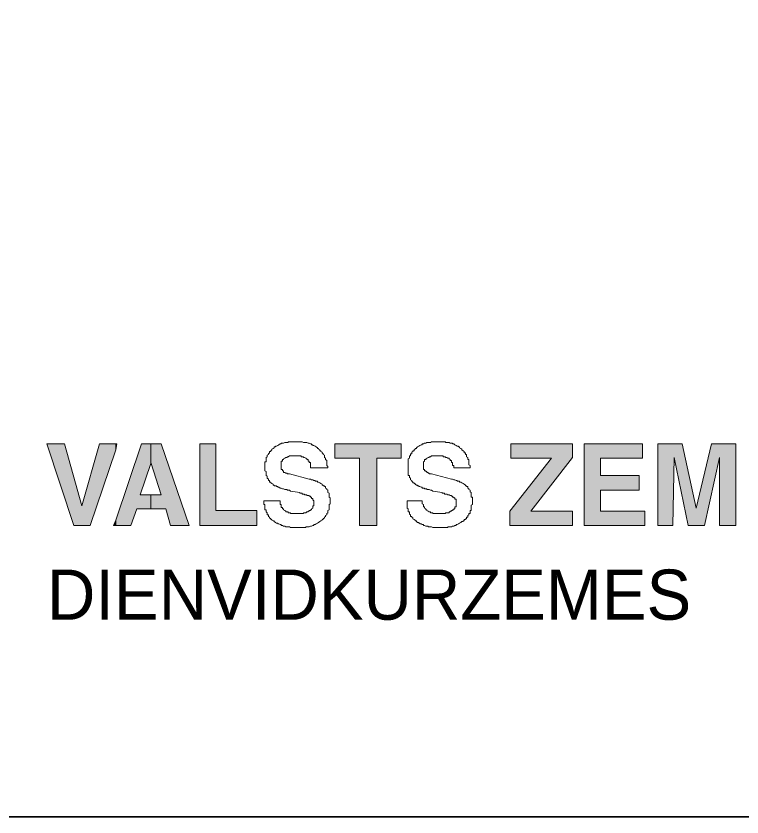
# Model space of a CAD drawing. Extents: x 308460 to 314812, y 245206 to 253414.
# Drawn here: x 314384.6 to 314574.6, y 245420.8 to 245630.3 of the extents above; entities that cross this region are included whole.
import ezdxf

# ---------------------------------------------------------------- set-up
doc = ezdxf.new("R2010")
doc.units = 0
doc.header["$LTSCALE"] = 11
doc.layers.add('57', color=7, linetype='Continuous', lineweight=13)

msp = doc.modelspace()

# ---------------------------------------------------------------- hatches: boundary and pattern name
at = {"layer": '57'}
for points in [[(314401.85, 245502.15), (314406.43, 245518.37), (314410.7, 245518.37), (314410.7, 245516.8), (314403.99, 245497.06), (314399.71, 245497.06), (314392.7, 245518.37), (314397.28, 245518.37)], [(314419.85, 245513.29), (314417.11, 245505.08), (314419.85, 245505.08), (314419.85, 245501.37), (314416.19, 245501.37), (314414.66, 245497.06), (314410.7, 245497.06), (314410.7, 245498.43), (314417.41, 245518.37), (314419.85, 245518.37)], [(314410.7, 245516.8), (314410.7, 245518.37), (314411.01, 245518.37)], [(314419.85, 245513.49), (314419.85, 245518.37), (314422.58, 245518.37), (314429.92, 245497.06), (314425.04, 245497.06), (314423.82, 245501.37), (314419.85, 245501.37), (314419.85, 245505.08), (314422.58, 245505.08)], [(314436.94, 245518.37), (314436.94, 245500.97), (314447.61, 245500.97), (314447.61, 245497.06), (314432.67, 245497.06), (314432.67, 245518.37)], [(314479.04, 245514.66), (314479.04, 245497.06), (314474.47, 245497.06), (314474.47, 245514.66), (314468.07, 245514.66), (314468.07, 245518.37), (314485.44, 245518.37), (314485.44, 245514.66)], [(314530.3, 245500.78), (314530.3, 245497.06), (314513.82, 245497.06), (314513.82, 245500.78), (314524.8, 245514.66), (314514.13, 245514.66), (314514.13, 245518.37), (314530.3, 245518.37), (314530.3, 245514.85), (314519.32, 245500.78)], [(314548.6, 245518.37), (314548.6, 245514.66), (314537.62, 245514.66), (314537.62, 245510.16), (314547.69, 245510.16), (314547.69, 245506.25), (314537.62, 245506.25), (314537.62, 245500.78), (314549.21, 245500.78), (314549.21, 245497.06), (314533.34, 245497.06), (314533.34, 245518.37)], [(314573.01, 245518.37), (314573.01, 245497.06), (314568.75, 245497.06), (314568.75, 245514.85), (314564.78, 245497.06), (314560.51, 245497.06), (314556.84, 245514.85), (314556.54, 245497.06), (314552.58, 245497.06), (314552.58, 245518.37), (314558.98, 245518.37), (314562.64, 245501.56), (314566.61, 245518.37)], [(314410.7, 245497.06), (314410.09, 245497.06), (314410.7, 245498.43)]]:
    msp.add_hatch(color=256, dxfattribs=at).paths.add_polyline_path(points)

# ---------------------------------------------------------------- linework, layer by layer
at = {"layer": '57', "lineweight": 35}
msp.add_lwpolyline([(314811.5, 253140.4), (312000.01, 253140.4), (312000.01, 245420.78), (314811.5, 245420.78)], close=True, dxfattribs=at)
at = {"layer": '57'}
for points in [[(314401.85, 245502.15), (314406.43, 245518.37), (314410.7, 245518.37), (314410.7, 245516.8), (314403.99, 245497.06), (314399.71, 245497.06), (314392.7, 245518.37), (314397.28, 245518.37)], [(314419.85, 245513.29), (314417.11, 245505.08), (314419.85, 245505.08), (314419.85, 245501.37), (314416.19, 245501.37), (314414.66, 245497.06), (314410.7, 245497.06), (314410.7, 245498.43), (314417.41, 245518.37), (314419.85, 245518.37)], [(314410.7, 245516.8), (314410.7, 245518.37), (314411.01, 245518.37)], [(314419.85, 245513.49), (314419.85, 245518.37), (314422.58, 245518.37), (314429.92, 245497.06), (314425.04, 245497.06), (314423.82, 245501.37), (314419.85, 245501.37), (314419.85, 245505.08), (314422.58, 245505.08)], [(314436.94, 245518.37), (314436.94, 245500.97), (314447.61, 245500.97), (314447.61, 245497.06), (314432.67, 245497.06), (314432.67, 245518.37)], [(314479.04, 245514.66), (314479.04, 245497.06), (314474.47, 245497.06), (314474.47, 245514.66), (314468.07, 245514.66), (314468.07, 245518.37), (314485.44, 245518.37), (314485.44, 245514.66)], [(314530.3, 245500.78), (314530.3, 245497.06), (314513.82, 245497.06), (314513.82, 245500.78), (314524.8, 245514.66), (314514.13, 245514.66), (314514.13, 245518.37), (314530.3, 245518.37), (314530.3, 245514.85), (314519.32, 245500.78)], [(314548.6, 245518.37), (314548.6, 245514.66), (314537.62, 245514.66), (314537.62, 245510.16), (314547.69, 245510.16), (314547.69, 245506.25), (314537.62, 245506.25), (314537.62, 245500.78), (314549.21, 245500.78), (314549.21, 245497.06), (314533.34, 245497.06), (314533.34, 245518.37)], [(314573.01, 245518.37), (314573.01, 245497.06), (314568.75, 245497.06), (314568.75, 245514.85), (314564.78, 245497.06), (314560.51, 245497.06), (314556.84, 245514.85), (314556.54, 245497.06), (314552.58, 245497.06), (314552.58, 245518.37), (314558.98, 245518.37), (314562.64, 245501.56), (314566.61, 245518.37)], [(314410.7, 245497.06), (314410.09, 245497.06), (314410.7, 245498.43)]]:
    msp.add_lwpolyline(points, close=True, dxfattribs=at)
for points in [[(314452.19, 245507.42), (314452.19, 245507.63), (314451.9, 245507.63), (314451.9, 245507.81), (314451.58, 245508.01), (314451.27, 245508.2), (314451.27, 245508.41), (314450.98, 245508.41), (314450.98, 245508.6), (314450.98, 245508.78), (314450.66, 245508.78), (314450.66, 245508.99), (314450.66, 245509.18), (314450.37, 245509.38), (314450.37, 245509.56), (314450.37, 245509.77), (314450.37, 245509.97), (314450.05, 245510.16), (314450.05, 245510.36), (314450.05, 245510.55), (314450.05, 245510.75), (314450.05, 245510.94), (314450.05, 245511.14), (314449.75, 245511.33), (314449.75, 245511.52), (314449.75, 245511.73), (314449.75, 245511.92), (314449.75, 245512.11), (314449.75, 245512.3), (314449.75, 245512.51), (314449.75, 245512.7), (314449.75, 245512.89), (314449.75, 245513.08), (314449.75, 245513.29), (314449.75, 245513.49), (314449.75, 245513.67), (314450.05, 245513.67), (314450.05, 245513.87), (314450.05, 245514.06), (314450.05, 245514.26), (314450.05, 245514.45), (314450.05, 245514.66), (314450.05, 245514.85), (314450.37, 245515.04), (314450.37, 245515.24), (314450.37, 245515.43), (314450.66, 245515.63), (314450.66, 245515.82), (314450.98, 245516.02), (314450.98, 245516.22), (314450.98, 245516.41), (314451.27, 245516.41), (314451.27, 245516.61), (314451.58, 245516.8), (314451.58, 245517), (314451.9, 245517.19), (314452.19, 245517.39), (314452.19, 245517.59), (314452.5, 245517.59), (314452.5, 245517.78), (314452.8, 245517.78), (314453.11, 245517.97), (314453.4, 245518.17), (314453.71, 245518.37), (314454.03, 245518.37), (314454.03, 245518.56), (314454.33, 245518.56), (314454.64, 245518.56), (314454.93, 245518.76), (314455.24, 245518.76), (314455.56, 245518.76), (314455.85, 245518.76), (314455.85, 245518.95), (314456.16, 245518.95), (314456.46, 245518.95), (314456.77, 245518.95), (314457.07, 245518.95), (314457.38, 245518.95), (314457.68, 245518.95), (314457.99, 245518.95), (314458.29, 245518.95), (314458.6, 245518.95), (314458.9, 245518.95), (314459.21, 245518.95), (314459.51, 245518.95), (314459.82, 245518.76), (314460.12, 245518.76), (314460.43, 245518.76), (314460.73, 245518.76), (314461.04, 245518.56), (314461.34, 245518.56), (314461.64, 245518.37), (314461.95, 245518.37), (314461.95, 245518.17), (314462.25, 245518.17), (314462.25, 245517.97), (314462.57, 245517.97), (314462.88, 245517.78), (314463.17, 245517.59), (314463.49, 245517.39), (314463.49, 245517.19)], [(314489.72, 245507.63), (314489.41, 245507.63), (314489.11, 245507.81), (314489.11, 245508.01), (314488.8, 245508.01), (314488.8, 245508.2), (314488.5, 245508.2), (314488.5, 245508.41), (314488.2, 245508.6), (314488.2, 245508.78), (314487.9, 245508.99), (314487.9, 245509.18), (314487.9, 245509.38), (314487.59, 245509.56), (314487.59, 245509.77), (314487.59, 245509.97), (314487.59, 245510.16), (314487.27, 245510.16), (314487.27, 245510.36), (314487.27, 245510.55), (314487.27, 245510.75), (314487.27, 245510.94), (314487.27, 245511.14), (314487.27, 245511.33), (314487.27, 245511.52), (314487.27, 245511.73), (314487.27, 245511.92), (314487.27, 245512.11), (314487.27, 245512.3), (314487.27, 245512.51), (314487.27, 245512.7), (314487.27, 245512.89), (314487.27, 245513.08), (314487.27, 245513.29), (314487.27, 245513.49), (314487.27, 245513.67), (314487.27, 245513.87), (314487.27, 245514.06), (314487.27, 245514.26), (314487.27, 245514.45), (314487.59, 245514.66), (314487.59, 245514.85), (314487.59, 245515.04), (314487.59, 245515.24), (314487.9, 245515.24), (314487.9, 245515.43), (314487.9, 245515.63), (314487.9, 245515.82), (314488.2, 245515.82), (314488.2, 245516.02), (314488.2, 245516.22), (314488.5, 245516.41), (314488.5, 245516.61), (314488.8, 245516.61), (314488.8, 245516.8), (314489.11, 245517), (314489.11, 245517.19), (314489.41, 245517.19), (314489.41, 245517.39), (314489.72, 245517.59), (314490.03, 245517.78), (314490.33, 245517.97), (314490.63, 245518.17), (314490.93, 245518.17), (314490.93, 245518.37), (314491.24, 245518.37), (314491.55, 245518.56), (314491.85, 245518.56), (314492.16, 245518.76), (314492.46, 245518.76), (314492.76, 245518.76), (314493.09, 245518.76), (314493.37, 245518.95), (314493.69, 245518.95), (314494, 245518.95), (314494.3, 245518.95), (314494.6, 245518.95), (314494.91, 245518.95), (314495.22, 245518.95), (314495.51, 245518.95), (314495.83, 245518.95), (314496.12, 245518.95), (314496.43, 245518.95), (314496.75, 245518.95), (314497.04, 245518.95), (314497.04, 245518.76), (314497.35, 245518.76), (314497.65, 245518.76), (314497.96, 245518.76), (314498.25, 245518.56), (314498.56, 245518.56), (314498.88, 245518.56), (314498.88, 245518.37), (314499.18, 245518.37), (314499.49, 245518.17), (314499.79, 245517.97), (314500.09, 245517.78), (314500.4, 245517.78), (314500.4, 245517.59), (314500.7, 245517.59), (314500.7, 245517.39)], [(314463.49, 245517.19), (314463.78, 245517.19), (314463.78, 245517), (314464.09, 245516.8), (314464.09, 245516.61), (314464.4, 245516.61), (314464.4, 245516.41), (314464.7, 245516.22), (314464.7, 245516.02), (314465.01, 245515.82), (314465.01, 245515.63), (314465.31, 245515.43), (314465.31, 245515.24), (314465.31, 245515.04), (314465.31, 245514.85), (314465.62, 245514.66), (314465.62, 245514.45), (314465.62, 245514.26), (314465.92, 245514.06), (314465.92, 245513.87), (314465.92, 245513.67), (314465.92, 245513.49), (314465.92, 245513.29), (314465.92, 245513.08), (314465.92, 245512.89), (314465.92, 245512.7), (314466.22, 245512.51), (314466.22, 245512.3), (314466.22, 245512.11), (314461.64, 245512.11), (314461.64, 245512.3), (314461.64, 245512.51), (314461.64, 245512.7), (314461.64, 245512.89), (314461.64, 245513.08), (314461.64, 245513.29), (314461.64, 245513.49), (314461.34, 245513.49), (314461.34, 245513.67), (314461.34, 245513.87), (314461.04, 245513.87), (314461.04, 245514.06), (314461.04, 245514.26), (314460.73, 245514.26), (314460.73, 245514.45), (314460.43, 245514.66), (314460.12, 245514.85), (314459.82, 245514.85), (314459.82, 245515.04), (314459.51, 245515.04), (314459.21, 245515.04), (314459.21, 245515.24), (314458.9, 245515.24), (314458.6, 245515.24), (314458.29, 245515.24), (314457.99, 245515.24), (314457.68, 245515.24), (314457.38, 245515.24), (314457.07, 245515.24), (314456.77, 245515.24), (314456.46, 245515.24), (314456.16, 245515.24), (314455.85, 245515.04), (314455.56, 245515.04), (314455.56, 245514.85), (314455.24, 245514.85), (314454.93, 245514.66), (314454.64, 245514.45), (314454.64, 245514.26), (314454.33, 245514.26), (314454.33, 245514.06), (314454.33, 245513.87), (314454.03, 245513.87), (314454.03, 245513.67), (314454.03, 245513.49), (314454.03, 245513.29), (314454.03, 245513.08), (314454.03, 245512.89), (314454.03, 245512.7), (314454.03, 245512.51), (314454.03, 245512.3), (314454.03, 245512.11), (314454.03, 245511.92), (314454.03, 245511.73), (314454.33, 245511.73), (314454.33, 245511.52), (314454.33, 245511.33), (314454.64, 245511.33), (314454.64, 245511.14), (314454.64, 245510.94), (314454.93, 245510.94), (314455.24, 245510.75), (314455.56, 245510.75), (314455.56, 245510.55), (314455.85, 245510.55), (314456.16, 245510.55), (314461.34, 245509.18), (314461.64, 245509.18), (314461.95, 245508.99), (314462.25, 245508.99), (314462.57, 245508.78)], [(314500.7, 245517.39), (314501.01, 245517.19), (314501.31, 245517), (314501.31, 245516.8), (314501.62, 245516.61), (314501.92, 245516.41), (314501.92, 245516.22), (314501.92, 245516.02), (314502.23, 245516.02), (314502.23, 245515.82), (314502.23, 245515.63), (314502.54, 245515.63), (314502.54, 245515.43), (314502.54, 245515.24), (314502.54, 245515.04), (314502.84, 245514.85), (314502.84, 245514.66), (314502.84, 245514.45), (314502.84, 245514.26), (314503.14, 245514.26), (314503.14, 245514.06), (314503.14, 245513.87), (314503.14, 245513.67), (314503.14, 245513.49), (314503.14, 245513.29), (314503.14, 245513.08), (314503.14, 245512.89), (314503.45, 245512.7), (314503.45, 245512.51), (314503.45, 245512.3), (314503.45, 245512.11), (314499.18, 245512.11), (314499.18, 245512.3), (314499.18, 245512.51), (314499.18, 245512.7), (314498.88, 245512.7), (314498.88, 245512.89), (314498.88, 245513.08), (314498.88, 245513.29), (314498.88, 245513.49), (314498.56, 245513.49), (314498.56, 245513.67), (314498.56, 245513.87), (314498.56, 245514.06), (314498.25, 245514.06), (314498.25, 245514.26), (314497.96, 245514.45), (314497.96, 245514.66), (314497.65, 245514.66), (314497.35, 245514.85), (314497.04, 245514.85), (314497.04, 245515.04), (314496.75, 245515.04), (314496.43, 245515.04), (314496.43, 245515.24), (314496.12, 245515.24), (314495.83, 245515.24), (314495.51, 245515.24), (314495.22, 245515.24), (314494.91, 245515.24), (314494.6, 245515.24), (314494.3, 245515.24), (314494, 245515.24), (314493.69, 245515.24), (314493.37, 245515.24), (314493.09, 245515.04), (314492.76, 245515.04), (314492.76, 245514.85), (314492.46, 245514.85), (314492.16, 245514.66), (314492.16, 245514.45), (314491.85, 245514.45), (314491.85, 245514.26), (314491.55, 245514.26), (314491.55, 245514.06), (314491.55, 245513.87), (314491.24, 245513.67), (314491.24, 245513.49), (314491.24, 245513.29), (314491.24, 245513.08), (314491.24, 245512.89), (314491.24, 245512.7), (314491.24, 245512.51), (314491.24, 245512.3), (314491.24, 245512.11), (314491.24, 245511.92), (314491.24, 245511.73), (314491.55, 245511.73), (314491.55, 245511.52), (314491.55, 245511.33), (314491.85, 245511.33), (314491.85, 245511.14), (314492.16, 245511.14), (314492.16, 245510.94), (314492.46, 245510.94), (314492.46, 245510.75), (314492.76, 245510.75), (314492.76, 245510.55), (314493.09, 245510.55), (314493.37, 245510.55), (314498.56, 245509.18)], [(314462.57, 245508.78), (314462.88, 245508.78), (314462.88, 245508.6), (314463.17, 245508.6), (314463.49, 245508.6), (314463.49, 245508.41), (314463.78, 245508.41), (314464.09, 245508.2), (314464.4, 245508.01), (314464.7, 245507.81), (314464.7, 245507.63), (314465.01, 245507.63), (314465.01, 245507.42), (314465.31, 245507.42), (314465.31, 245507.23), (314465.62, 245507.23), (314465.62, 245507.03), (314465.62, 245506.83), (314465.92, 245506.64), (314465.92, 245506.44), (314466.22, 245506.25), (314466.22, 245506.05), (314466.22, 245505.86), (314466.22, 245505.67), (314466.53, 245505.47), (314466.53, 245505.27), (314466.53, 245505.08), (314466.53, 245504.88), (314466.53, 245504.69), (314466.53, 245504.49), (314466.84, 245504.3), (314466.84, 245504.1), (314466.84, 245503.9), (314466.84, 245503.71), (314466.84, 245503.52), (314466.84, 245503.31), (314466.84, 245503.13), (314466.84, 245502.93), (314466.84, 245502.74), (314466.53, 245502.53), (314466.53, 245502.33), (314466.53, 245502.15), (314466.53, 245501.96), (314466.53, 245501.75), (314466.53, 245501.56), (314466.53, 245501.37), (314466.53, 245501.16), (314466.22, 245500.97), (314466.22, 245500.78), (314466.22, 245500.59), (314466.22, 245500.38), (314465.92, 245500.2), (314465.92, 245500), (314465.92, 245499.8), (314465.62, 245499.61), (314465.62, 245499.41), (314465.31, 245499.22), (314465.31, 245499.02), (314465.01, 245498.82), (314465.01, 245498.63), (314464.7, 245498.63), (314464.7, 245498.43), (314464.4, 245498.24), (314464.09, 245498.04), (314463.78, 245497.85), (314463.49, 245497.65), (314463.17, 245497.46), (314462.88, 245497.26), (314462.57, 245497.26), (314462.57, 245497.06), (314462.25, 245497.06), (314461.95, 245496.87), (314461.64, 245496.87), (314461.34, 245496.67), (314461.04, 245496.67), (314460.73, 245496.67), (314460.43, 245496.67), (314460.43, 245496.48), (314460.12, 245496.48), (314459.82, 245496.48), (314459.51, 245496.48), (314459.21, 245496.48), (314458.9, 245496.48), (314458.6, 245496.48), (314458.29, 245496.48), (314457.99, 245496.48), (314457.68, 245496.48), (314457.38, 245496.48), (314457.07, 245496.48), (314456.77, 245496.48), (314456.46, 245496.48), (314456.16, 245496.67), (314455.85, 245496.67), (314455.56, 245496.67), (314455.24, 245496.67), (314454.93, 245496.87), (314454.64, 245496.87), (314454.33, 245497.06), (314454.03, 245497.06), (314454.03, 245497.26), (314453.71, 245497.26)], [(314498.56, 245509.18), (314498.88, 245509.18), (314499.18, 245508.99), (314499.49, 245508.99), (314499.79, 245508.78), (314500.09, 245508.78), (314500.09, 245508.6), (314500.4, 245508.6), (314500.7, 245508.6), (314500.7, 245508.41), (314501.01, 245508.41), (314501.31, 245508.2), (314501.62, 245508.01), (314501.92, 245507.81), (314502.23, 245507.63), (314502.23, 245507.42), (314502.54, 245507.42), (314502.54, 245507.23), (314502.84, 245507.23), (314502.84, 245507.03), (314502.84, 245506.83), (314503.14, 245506.64), (314503.14, 245506.44), (314503.45, 245506.25), (314503.45, 245506.05), (314503.45, 245505.86), (314503.75, 245505.67), (314503.75, 245505.47), (314503.75, 245505.27), (314503.75, 245505.08), (314503.75, 245504.88), (314503.75, 245504.69), (314503.75, 245504.49), (314504.07, 245504.49), (314504.07, 245504.3), (314504.07, 245504.1), (314504.07, 245503.9), (314504.07, 245503.71), (314504.07, 245503.52), (314504.07, 245503.31), (314504.07, 245503.13), (314504.07, 245502.93), (314504.07, 245502.74), (314504.07, 245502.53), (314503.75, 245502.33), (314503.75, 245502.15), (314503.75, 245501.96), (314503.75, 245501.75), (314503.75, 245501.56), (314503.75, 245501.37), (314503.75, 245501.16), (314503.75, 245500.97), (314503.45, 245500.97), (314503.45, 245500.78), (314503.45, 245500.59), (314503.45, 245500.38), (314503.45, 245500.2), (314503.14, 245500.2), (314503.14, 245500), (314503.14, 245499.8), (314502.84, 245499.61), (314502.84, 245499.41), (314502.84, 245499.22), (314502.54, 245499.22), (314502.54, 245499.02), (314502.54, 245498.82), (314502.23, 245498.82), (314502.23, 245498.63), (314501.92, 245498.63), (314501.92, 245498.43), (314501.92, 245498.24), (314501.62, 245498.24), (314501.62, 245498.04), (314501.31, 245498.04), (314501.01, 245497.85), (314500.7, 245497.65), (314500.4, 245497.46), (314500.09, 245497.26), (314499.79, 245497.26), (314499.79, 245497.06), (314499.49, 245497.06), (314499.18, 245496.87), (314498.88, 245496.87), (314498.56, 245496.67), (314498.25, 245496.67), (314497.96, 245496.67), (314497.65, 245496.67), (314497.65, 245496.48), (314497.35, 245496.48), (314497.04, 245496.48), (314496.75, 245496.48), (314496.43, 245496.48), (314496.12, 245496.48), (314495.83, 245496.48), (314495.51, 245496.48), (314495.22, 245496.48), (314494.91, 245496.48), (314494.6, 245496.48), (314494.3, 245496.48), (314494, 245496.48), (314493.69, 245496.48)], [(314449.46, 245503.52), (314453.71, 245503.52), (314453.71, 245503.31), (314453.71, 245503.13), (314453.71, 245502.93), (314453.71, 245502.74), (314453.71, 245502.53), (314454.03, 245502.53), (314454.03, 245502.33), (314454.03, 245502.15), (314454.03, 245501.96), (314454.03, 245501.75), (314454.33, 245501.75), (314454.33, 245501.56), (314454.33, 245501.37), (314454.64, 245501.37), (314454.64, 245501.16), (314454.93, 245500.97), (314455.24, 245500.78), (314455.24, 245500.59), (314455.56, 245500.59), (314455.85, 245500.59), (314455.85, 245500.38), (314456.16, 245500.38), (314456.46, 245500.38), (314456.46, 245500.2), (314456.77, 245500.2), (314457.07, 245500.2), (314457.38, 245500.2), (314457.68, 245500.2), (314457.99, 245500.2), (314458.29, 245500.2), (314458.6, 245500.2), (314458.9, 245500.2), (314459.21, 245500.2), (314459.51, 245500.2), (314459.82, 245500.2), (314459.82, 245500.38), (314460.12, 245500.38), (314460.43, 245500.38), (314460.73, 245500.59), (314461.04, 245500.59), (314461.04, 245500.78), (314461.34, 245500.78), (314461.34, 245500.97), (314461.64, 245500.97), (314461.64, 245501.16), (314461.95, 245501.16), (314461.95, 245501.37), (314462.25, 245501.56), (314462.25, 245501.75), (314462.25, 245501.96), (314462.25, 245502.15), (314462.57, 245502.15), (314462.57, 245502.33), (314462.57, 245502.53), (314462.57, 245502.74), (314462.57, 245502.93), (314462.57, 245503.13), (314462.57, 245503.31), (314462.57, 245503.52), (314462.25, 245503.71), (314462.25, 245503.9), (314462.25, 245504.1), (314461.95, 245504.1), (314461.95, 245504.3), (314461.95, 245504.49), (314461.64, 245504.49), (314461.64, 245504.69), (314461.34, 245504.69), (314461.34, 245504.88), (314461.04, 245504.88), (314460.73, 245504.88), (314460.73, 245505.08), (314460.43, 245505.08), (314460.12, 245505.08), (314460.12, 245505.27), (314459.82, 245505.27), (314459.51, 245505.27), (314459.51, 245505.47), (314459.21, 245505.47), (314458.9, 245505.47), (314458.9, 245505.67), (314456.46, 245506.05), (314456.16, 245506.25), (314455.85, 245506.25), (314455.56, 245506.25), (314455.56, 245506.44), (314455.24, 245506.44), (314454.93, 245506.44), (314454.64, 245506.64), (314454.33, 245506.64), (314454.03, 245506.83), (314453.71, 245506.83), (314453.4, 245507.03), (314453.11, 245507.03), (314453.11, 245507.23), (314452.8, 245507.23), (314452.8, 245507.42), (314452.5, 245507.42), (314452.19, 245507.42)], [(314486.98, 245503.52), (314490.93, 245503.52), (314490.93, 245503.31), (314490.93, 245503.13), (314490.93, 245502.93), (314490.93, 245502.74), (314491.24, 245502.53), (314491.24, 245502.33), (314491.24, 245502.15), (314491.24, 245501.96), (314491.55, 245501.96), (314491.55, 245501.75), (314491.55, 245501.56), (314491.85, 245501.37), (314491.85, 245501.16), (314492.16, 245501.16), (314492.16, 245500.97), (314492.46, 245500.78), (314492.76, 245500.59), (314493.09, 245500.59), (314493.09, 245500.38), (314493.37, 245500.38), (314493.69, 245500.38), (314493.69, 245500.2), (314494, 245500.2), (314494.3, 245500.2), (314494.6, 245500.2), (314494.91, 245500.2), (314495.22, 245500.2), (314495.51, 245500.2), (314495.83, 245500.2), (314496.12, 245500.2), (314496.43, 245500.2), (314496.75, 245500.2), (314497.04, 245500.2), (314497.04, 245500.38), (314497.35, 245500.38), (314497.65, 245500.38), (314497.96, 245500.38), (314497.96, 245500.59), (314498.25, 245500.59), (314498.25, 245500.78), (314498.56, 245500.78), (314498.56, 245500.97), (314498.88, 245500.97), (314498.88, 245501.16), (314499.18, 245501.16), (314499.18, 245501.37), (314499.49, 245501.37), (314499.49, 245501.56), (314499.49, 245501.75), (314499.49, 245501.96), (314499.79, 245501.96), (314499.79, 245502.15), (314499.79, 245502.33), (314499.79, 245502.53), (314499.79, 245502.74), (314499.79, 245502.93), (314499.79, 245503.13), (314499.79, 245503.31), (314499.79, 245503.52), (314499.79, 245503.71), (314499.79, 245503.9), (314499.49, 245503.9), (314499.49, 245504.1), (314499.49, 245504.3), (314499.18, 245504.3), (314499.18, 245504.49), (314498.88, 245504.49), (314498.88, 245504.69), (314498.56, 245504.69), (314498.56, 245504.88), (314498.25, 245504.88), (314497.96, 245505.08), (314497.65, 245505.08), (314497.35, 245505.27), (314497.04, 245505.27), (314496.75, 245505.27), (314496.75, 245505.47), (314496.43, 245505.47), (314496.12, 245505.47), (314496.12, 245505.67), (314493.69, 245506.05), (314493.37, 245506.25), (314493.09, 245506.25), (314492.76, 245506.44), (314492.46, 245506.44), (314492.16, 245506.44), (314492.16, 245506.64), (314491.85, 245506.64), (314491.55, 245506.64), (314491.55, 245506.83), (314491.24, 245506.83), (314490.93, 245506.83), (314490.93, 245507.03), (314490.63, 245507.03), (314490.33, 245507.23), (314490.03, 245507.23), (314490.03, 245507.42), (314489.72, 245507.42), (314489.72, 245507.63)], [(314453.71, 245497.26), (314453.4, 245497.46), (314453.11, 245497.46), (314453.11, 245497.65), (314452.8, 245497.65), (314452.5, 245497.85), (314452.19, 245498.04), (314452.19, 245498.24), (314451.9, 245498.24), (314451.58, 245498.43), (314451.58, 245498.63), (314451.27, 245498.63), (314451.27, 245498.82), (314450.98, 245499.02), (314450.98, 245499.22), (314450.66, 245499.41), (314450.66, 245499.61), (314450.66, 245499.8), (314450.37, 245499.8), (314450.37, 245500), (314450.37, 245500.2), (314450.37, 245500.38), (314450.05, 245500.59), (314450.05, 245500.78), (314450.05, 245500.97), (314450.05, 245501.16), (314449.75, 245501.16), (314449.75, 245501.37), (314449.75, 245501.56), (314449.75, 245501.75), (314449.75, 245501.96), (314449.75, 245502.15), (314449.75, 245502.33), (314449.75, 245502.53), (314449.46, 245502.53), (314449.46, 245502.74), (314449.46, 245502.93), (314449.46, 245503.13), (314449.46, 245503.31), (314449.46, 245503.52)], [(314493.69, 245496.48), (314493.37, 245496.67), (314493.09, 245496.67), (314492.76, 245496.67), (314492.46, 245496.67), (314492.46, 245496.87), (314492.16, 245496.87), (314491.85, 245496.87), (314491.55, 245497.06), (314491.24, 245497.06), (314491.24, 245497.26), (314490.93, 245497.26), (314490.63, 245497.46), (314490.33, 245497.46), (314490.33, 245497.65), (314490.03, 245497.65), (314490.03, 245497.85), (314489.72, 245497.85), (314489.41, 245498.04), (314489.41, 245498.24), (314489.11, 245498.24), (314489.11, 245498.43), (314488.8, 245498.63), (314488.5, 245498.82), (314488.5, 245499.02), (314488.2, 245499.22), (314488.2, 245499.41), (314487.9, 245499.41), (314487.9, 245499.61), (314487.9, 245499.8), (314487.59, 245500), (314487.59, 245500.2), (314487.59, 245500.38), (314487.59, 245500.59), (314487.27, 245500.59), (314487.27, 245500.78), (314487.27, 245500.97), (314487.27, 245501.16), (314487.27, 245501.37), (314486.98, 245501.56), (314486.98, 245501.75), (314486.98, 245501.96), (314486.98, 245502.15), (314486.98, 245502.33), (314486.98, 245502.53), (314486.98, 245502.74), (314486.98, 245502.93), (314486.98, 245503.13), (314486.98, 245503.31), (314486.98, 245503.52)]]:
    msp.add_lwpolyline(points, dxfattribs=at)

# ---------------------------------------------------------------- texts
msp.add_text('DIENVIDKURZEMES', height=13.12, dxfattribs=at).set_placement((314392.7, 245472.39))

doc.saveas('drawing.dxf')
